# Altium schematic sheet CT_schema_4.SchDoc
size 300 x 247 mm
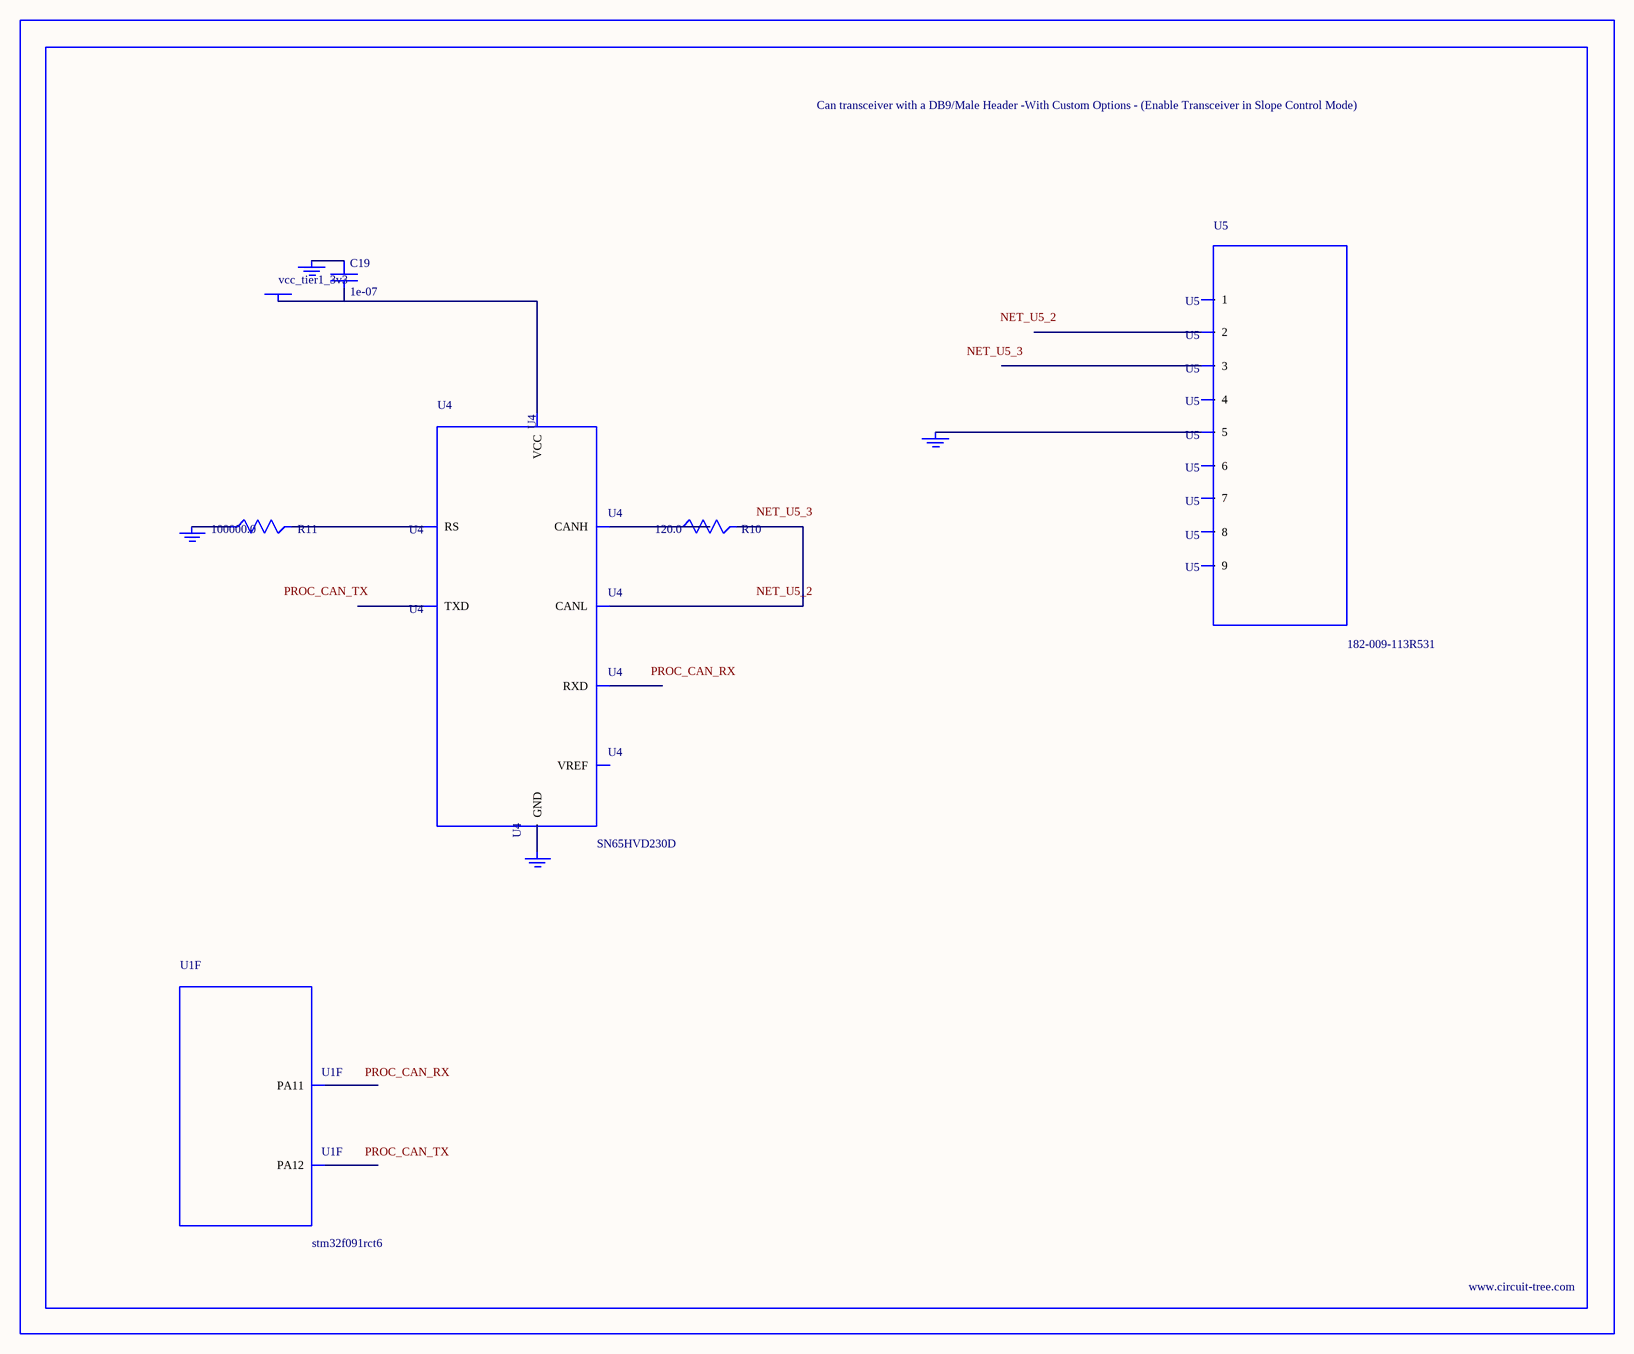
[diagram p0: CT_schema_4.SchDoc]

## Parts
BORDER3  (no value)
C19  1e-07  [C0402]
GND_INSTANCE_3_0  (no value)
GND_INSTANCE_3_1  (no value)
GND_INSTANCE_3_2  (no value)
GND_INSTANCE_3_3  (no value)
POWER_INSTANCE_3_0  vcc_tier1_3v3
R10  120.0  [R0603]
R11  100000.0  [R0603]
U1  stm32f091rct6  [LQFP64]  (part F of 7)
U4  SN65HVD230D  [SOIC-8]
U5  182-009-113R531  [182-009-MALE]

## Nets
NetC19_1: C19.1 GND_INSTANCE_3_0.0(GND)
NetC19_2: C19.2 POWER_INSTANCE_3_0.0(PWR) U4.3(VCC)
NetGND_INSTANCE_3_1_0: GND_INSTANCE_3_1.0(GND) R11.1
NetGND_INSTANCE_3_2_0: GND_INSTANCE_3_2.0(GND) U4.2(GND)
NetGND_INSTANCE_3_3_0: GND_INSTANCE_3_3.0(GND) U5.5
NetR10_1: R10.1 U4.7(CANH)
NetR10_2: R10.2 U4.6(CANL)
NetR11_2: R11.2 U4.8(RS)

Not connected (* = marked no-connect by the designer): U1 44(PA11) 45(PA12); U4 1(TXD) 4(RXD) 5(VREF); U5 1 2 3 4 6 7 8 9

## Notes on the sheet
- Labels drawn without touching a wire or pin: NET_U5_2, NET_U5_3, PROC_CAN_RX, PROC_CAN_TX

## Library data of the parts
BORDER3 = BORDER_PAGE3
C19 = C0402C104K3RACTU
GND_INSTANCE_3_0-GND_INSTANCE_3_3 = GND
POWER_INSTANCE_3_0 = PWR
R10 = RC0603JR-07120RL
R11 = RC0603JR-07100KL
